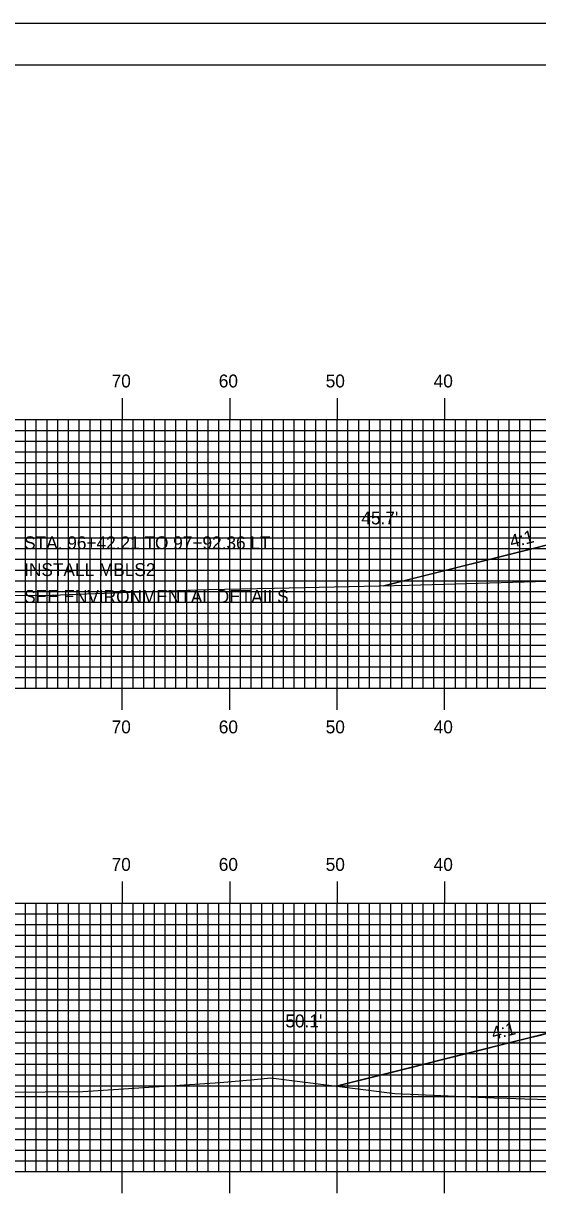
# Model space of a CAD drawing. Extents: x 1765726 to 1766069, y 442591 to 442811.
# Drawn here: x 1765812.7 to 1765860.5, y 442701.2 to 442810.5 of the extents above; entities that cross this region are included whole.
import ezdxf

# ---------------------------------------------------------------- set-up
doc = ezdxf.new("R2010")
doc.units = 0
for name, color, linetype in [('ANNOTATION', 7, 'Continuous'), ('BORDER', 7, 'Continuous'), ('D_Roadway_Centerline', 7, 'Continuous'), ('D_Roadway_SlopeLines', 7, 'Continuous'), ('D_Text_Standard', 7, 'Continuous'), ('H_V ANNOTATION', 7, 'Continuous'), ('MAJOR', 7, 'Continuous'), ('MINOR', 7, 'Continuous'), ('PLOT BOUNDARY', 7, 'Continuous'), ('S_Roadway_Centerline', 7, 'Continuous')]:
    doc.layers.add(name, color=color, linetype=linetype)

msp = doc.modelspace()

# ---------------------------------------------------------------- linework, layer by layer
at = {"layer": 'BORDER'}
msp.add_lwpolyline([(1765742.28, 442596.67), (1766062.28, 442596.67), (1766062.28, 442806.67), (1765742.28, 442806.67)], close=True, dxfattribs=at)
at = {"layer": 'D_Roadway_Centerline'}
for points in [[(1765846.22, 442758.2), (1765848.67, 442758.82), (1765859.88, 442761.62), (1765859.88, 442761.62), (1765861.71, 442762.08), (1765861.71, 442762.08), (1765864.22, 442762.7), (1765871.88, 442764.62), (1765871.88, 442764.62), (1765871.89, 442764.62), (1765879.88, 442764.94), (1765890.42, 442764.71), (1765891.88, 442764.67), (1765891.89, 442764.67), (1765903.88, 442764.41), (1765903.89, 442764.41), (1765907.46, 442764.27), (1765911.88, 442764.09), (1765922.06, 442761.55), (1765930.71, 442759.38), (1765930.71, 442759.38)], [(1765841.8, 442711.63), (1765845.9, 442712.65), (1765859.88, 442716.15), (1765860.72, 442716.36), (1765861.71, 442716.61), (1765865.41, 442717.53), (1765871.88, 442719.15), (1765871.88, 442719.15), (1765878.83, 442719.43), (1765879.88, 442719.47), (1765883.45, 442719.39), (1765891.88, 442719.21), (1765903.88, 442718.94), (1765903.89, 442718.94), (1765909.96, 442718.7), (1765911.88, 442718.62), (1765922.06, 442716.08), (1765935.37, 442712.75)]]:
    msp.add_lwpolyline(points, dxfattribs=at)
at = {"layer": 'D_Roadway_SlopeLines'}
for points in [[(1765871.88, 442764.62), (1765861.71, 442762.08), (1765859.88, 442761.62), (1765846.22, 442758.2)], [(1765871.88, 442719.15), (1765861.71, 442716.61), (1765859.88, 442716.15), (1765841.8, 442711.63)]]:
    msp.add_lwpolyline(points, dxfattribs=at)
at = {"layer": 'MAJOR'}
for p, q in [((1765821.88, 442775.67), (1765821.88, 442773.67)), ((1765831.88, 442775.67), (1765831.88, 442773.67)), ((1765841.88, 442775.67), (1765841.88, 442773.67)), ((1765851.88, 442775.67), (1765851.88, 442773.67)), ((1765751.88, 442773.67), (1766031.88, 442773.67)), ((1765751.88, 442773.67), (1766031.88, 442773.67)), ((1765821.88, 442748.67), (1765821.88, 442773.67)), ((1765831.88, 442748.67), (1765831.88, 442773.67)), ((1765841.88, 442748.67), (1765841.88, 442773.67)), ((1765851.88, 442748.67), (1765851.88, 442773.67)), ((1765751.88, 442768.67), (1766031.88, 442768.67)), ((1765751.88, 442763.67), (1766031.88, 442763.67)), ((1765751.88, 442758.67), (1766031.88, 442758.67)), ((1765751.88, 442753.67), (1766031.88, 442753.67)), ((1765751.88, 442748.67), (1766031.88, 442748.67)), ((1765751.88, 442748.67), (1766031.88, 442748.67)), ((1765821.88, 442746.66), (1765821.88, 442748.67)), ((1765831.88, 442746.66), (1765831.88, 442748.67)), ((1765841.88, 442746.66), (1765841.88, 442748.67)), ((1765851.88, 442746.66), (1765851.88, 442748.67)), ((1765821.88, 442730.67), (1765821.88, 442728.67)), ((1765831.88, 442730.67), (1765831.88, 442728.67)), ((1765841.88, 442730.67), (1765841.88, 442728.67)), ((1765851.88, 442730.67), (1765851.88, 442728.67)), ((1765751.88, 442728.67), (1766031.88, 442728.67)), ((1765751.88, 442728.67), (1766031.88, 442728.67)), ((1765821.88, 442703.67), (1765821.88, 442728.67)), ((1765831.88, 442703.67), (1765831.88, 442728.67)), ((1765841.88, 442703.67), (1765841.88, 442728.67)), ((1765851.88, 442703.67), (1765851.88, 442728.67)), ((1765751.88, 442723.67), (1766031.88, 442723.67)), ((1765751.88, 442718.67), (1766031.88, 442718.67)), ((1765751.88, 442713.67), (1766031.88, 442713.67)), ((1765751.88, 442708.67), (1766031.88, 442708.67)), ((1765751.88, 442703.67), (1766031.88, 442703.67)), ((1765751.88, 442703.67), (1766031.88, 442703.67)), ((1765821.88, 442701.66), (1765821.88, 442703.67)), ((1765831.88, 442701.66), (1765831.88, 442703.67)), ((1765841.88, 442701.66), (1765841.88, 442703.67)), ((1765851.88, 442701.66), (1765851.88, 442703.67))]:
    msp.add_line(p, q, dxfattribs=at)
at = {"layer": 'MINOR'}
for p, q in [((1765812.88, 442748.67), (1765812.88, 442773.67)), ((1765813.88, 442748.67), (1765813.88, 442773.67)), ((1765814.88, 442748.67), (1765814.88, 442773.67)), ((1765815.88, 442748.67), (1765815.88, 442773.67)), ((1765816.88, 442748.67), (1765816.88, 442773.67)), ((1765817.88, 442748.67), (1765817.88, 442773.67)), ((1765818.88, 442748.67), (1765818.88, 442773.67)), ((1765819.88, 442748.67), (1765819.88, 442773.67)), ((1765820.88, 442748.67), (1765820.88, 442773.67)), ((1765822.88, 442748.67), (1765822.88, 442773.67)), ((1765823.88, 442748.67), (1765823.88, 442773.67)), ((1765824.88, 442748.67), (1765824.88, 442773.67)), ((1765825.88, 442748.67), (1765825.88, 442773.67)), ((1765826.88, 442748.67), (1765826.88, 442773.67)), ((1765827.88, 442748.67), (1765827.88, 442773.67)), ((1765828.88, 442748.67), (1765828.88, 442773.67)), ((1765829.88, 442748.67), (1765829.88, 442773.67)), ((1765830.88, 442748.67), (1765830.88, 442773.67)), ((1765832.88, 442748.67), (1765832.88, 442773.67)), ((1765833.88, 442748.67), (1765833.88, 442773.67)), ((1765834.88, 442748.67), (1765834.88, 442773.67)), ((1765835.88, 442748.67), (1765835.88, 442773.67)), ((1765836.88, 442748.67), (1765836.88, 442773.67)), ((1765837.88, 442748.67), (1765837.88, 442773.67)), ((1765838.88, 442748.67), (1765838.88, 442773.67)), ((1765839.88, 442748.67), (1765839.88, 442773.67)), ((1765840.88, 442748.67), (1765840.88, 442773.67)), ((1765842.88, 442748.67), (1765842.88, 442773.67)), ((1765843.88, 442748.67), (1765843.88, 442773.67)), ((1765844.88, 442748.67), (1765844.88, 442773.67)), ((1765845.88, 442748.67), (1765845.88, 442773.67)), ((1765846.88, 442748.67), (1765846.88, 442773.67)), ((1765847.88, 442748.67), (1765847.88, 442773.67)), ((1765848.88, 442748.67), (1765848.88, 442773.67)), ((1765849.88, 442748.67), (1765849.88, 442773.67)), ((1765850.88, 442748.67), (1765850.88, 442773.67)), ((1765852.88, 442748.67), (1765852.88, 442773.67)), ((1765853.88, 442748.67), (1765853.88, 442773.67)), ((1765854.88, 442748.67), (1765854.88, 442773.67)), ((1765855.88, 442748.67), (1765855.88, 442773.67)), ((1765856.88, 442748.67), (1765856.88, 442773.67)), ((1765857.88, 442748.67), (1765857.88, 442773.67)), ((1765858.88, 442748.67), (1765858.88, 442773.67)), ((1765859.88, 442748.67), (1765859.88, 442773.67)), ((1765751.88, 442772.67), (1766031.88, 442772.67)), ((1765751.88, 442771.67), (1766031.88, 442771.67)), ((1765751.88, 442770.67), (1766031.88, 442770.67)), ((1765751.88, 442769.67), (1766031.88, 442769.67)), ((1765751.88, 442767.67), (1766031.88, 442767.67)), ((1765751.88, 442766.67), (1766031.88, 442766.67)), ((1765751.88, 442765.67), (1766031.88, 442765.67)), ((1765751.88, 442764.67), (1766031.88, 442764.67)), ((1765751.88, 442762.67), (1766031.88, 442762.67)), ((1765751.88, 442761.67), (1766031.88, 442761.67)), ((1765751.88, 442760.67), (1766031.88, 442760.67)), ((1765751.88, 442759.67), (1766031.88, 442759.67)), ((1765751.88, 442757.67), (1766031.88, 442757.67)), ((1765751.88, 442756.67), (1766031.88, 442756.67)), ((1765751.88, 442755.67), (1766031.88, 442755.67)), ((1765751.88, 442754.67), (1766031.88, 442754.67)), ((1765751.88, 442752.67), (1766031.88, 442752.67)), ((1765751.88, 442751.67), (1766031.88, 442751.67)), ((1765751.88, 442750.67), (1766031.88, 442750.67)), ((1765751.88, 442749.67), (1766031.88, 442749.67)), ((1765812.88, 442703.67), (1765812.88, 442728.67)), ((1765813.88, 442703.67), (1765813.88, 442728.67)), ((1765814.88, 442703.67), (1765814.88, 442728.67)), ((1765815.88, 442703.67), (1765815.88, 442728.67)), ((1765816.88, 442703.67), (1765816.88, 442728.67)), ((1765817.88, 442703.67), (1765817.88, 442728.67)), ((1765818.88, 442703.67), (1765818.88, 442728.67)), ((1765819.88, 442703.67), (1765819.88, 442728.67)), ((1765820.88, 442703.67), (1765820.88, 442728.67)), ((1765822.88, 442703.67), (1765822.88, 442728.67)), ((1765823.88, 442703.67), (1765823.88, 442728.67)), ((1765824.88, 442703.67), (1765824.88, 442728.67)), ((1765825.88, 442703.67), (1765825.88, 442728.67)), ((1765826.88, 442703.67), (1765826.88, 442728.67)), ((1765827.88, 442703.67), (1765827.88, 442728.67)), ((1765828.88, 442703.67), (1765828.88, 442728.67)), ((1765829.88, 442703.67), (1765829.88, 442728.67)), ((1765830.88, 442703.67), (1765830.88, 442728.67)), ((1765832.88, 442703.67), (1765832.88, 442728.67)), ((1765833.88, 442703.67), (1765833.88, 442728.67)), ((1765834.88, 442703.67), (1765834.88, 442728.67)), ((1765835.88, 442703.67), (1765835.88, 442728.67)), ((1765836.88, 442703.67), (1765836.88, 442728.67)), ((1765837.88, 442703.67), (1765837.88, 442728.67)), ((1765838.88, 442703.67), (1765838.88, 442728.67)), ((1765839.88, 442703.67), (1765839.88, 442728.67)), ((1765840.88, 442703.67), (1765840.88, 442728.67)), ((1765842.88, 442703.67), (1765842.88, 442728.67)), ((1765843.88, 442703.67), (1765843.88, 442728.67)), ((1765844.88, 442703.67), (1765844.88, 442728.67)), ((1765845.88, 442703.67), (1765845.88, 442728.67)), ((1765846.88, 442703.67), (1765846.88, 442728.67)), ((1765847.88, 442703.67), (1765847.88, 442728.67)), ((1765848.88, 442703.67), (1765848.88, 442728.67)), ((1765849.88, 442703.67), (1765849.88, 442728.67)), ((1765850.88, 442703.67), (1765850.88, 442728.67)), ((1765852.88, 442703.67), (1765852.88, 442728.67)), ((1765853.88, 442703.67), (1765853.88, 442728.67)), ((1765854.88, 442703.67), (1765854.88, 442728.67)), ((1765855.88, 442703.67), (1765855.88, 442728.67)), ((1765856.88, 442703.67), (1765856.88, 442728.67)), ((1765857.88, 442703.67), (1765857.88, 442728.67)), ((1765858.88, 442703.67), (1765858.88, 442728.67)), ((1765859.88, 442703.67), (1765859.88, 442728.67)), ((1765751.88, 442727.67), (1766031.88, 442727.67)), ((1765751.88, 442726.67), (1766031.88, 442726.67)), ((1765751.88, 442725.67), (1766031.88, 442725.67)), ((1765751.88, 442724.67), (1766031.88, 442724.67)), ((1765751.88, 442722.67), (1766031.88, 442722.67)), ((1765751.88, 442721.67), (1766031.88, 442721.67)), ((1765751.88, 442720.67), (1766031.88, 442720.67)), ((1765751.88, 442719.67), (1766031.88, 442719.67)), ((1765751.88, 442717.67), (1766031.88, 442717.67)), ((1765751.88, 442716.67), (1766031.88, 442716.67)), ((1765751.88, 442715.67), (1766031.88, 442715.67)), ((1765751.88, 442714.67), (1766031.88, 442714.67)), ((1765751.88, 442712.67), (1766031.88, 442712.67)), ((1765751.88, 442711.67), (1766031.88, 442711.67)), ((1765751.88, 442710.67), (1766031.88, 442710.67)), ((1765751.88, 442709.67), (1766031.88, 442709.67)), ((1765751.88, 442707.67), (1766031.88, 442707.67)), ((1765751.88, 442706.67), (1766031.88, 442706.67)), ((1765751.88, 442705.67), (1766031.88, 442705.67)), ((1765751.88, 442704.67), (1766031.88, 442704.67))]:
    msp.add_line(p, q, dxfattribs=at)
at = {"layer": 'PLOT BOUNDARY'}
msp.add_lwpolyline([(1765726.1, 442590.55), (1766066.1, 442590.55), (1766066.1, 442810.55), (1765726.1, 442810.55)], close=True, dxfattribs=at)
at = {"layer": 'S_Roadway_Centerline'}
for points in [[(1765811.71, 442757.29), (1765815.32, 442757.33), (1765823.43, 442757.64), (1765829.83, 442757.85), (1765836.03, 442758), (1765848.57, 442758.25), (1765860.32, 442758.61), (1765866.57, 442758.79)], [(1765811.19, 442711.08), (1765818.21, 442711.14), (1765830.98, 442711.97), (1765834.15, 442712.24), (1765835.72, 442712.4), (1765847.23, 442710.94), (1765848.7, 442710.88), (1765855.02, 442710.61), (1765855.66, 442710.58), (1765856.53, 442710.55), (1765857.71, 442710.51), (1765859.34, 442710.46), (1765861.7, 442710.38)]]:
    msp.add_lwpolyline(points, dxfattribs=at)

# ---------------------------------------------------------------- texts
at = {"layer": 'ANNOTATION'}
for rotation, p in [(14.035, (1765858.11, 442761.73)), (14.0394, (1765856.41, 442715.94))]:
    msp.add_text('4:1', height=1.2, rotation=rotation, dxfattribs=at).set_placement(p)
at = {"layer": 'D_Text_Standard'}
for s, p in [("45.7'", (1765844.13, 442763.92)), ('STA. 96+42.21 TO 97+92.36 LT.', (1765812.75, 442761.61)), ('INSTALL MBLS2', (1765812.75, 442759.11)), ('SEE ENVIRONMENTAL DETAILS', (1765812.75, 442756.61)), ("50.1'", (1765837.06, 442717.1))]:
    msp.add_text(s, height=1.2, dxfattribs=at).set_placement(p)
at = {"layer": 'H_V ANNOTATION'}
for s, p in [('70', (1765820.89, 442776.67)), ('60', (1765830.86, 442776.67)), ('50', (1765840.81, 442776.67)), ('40', (1765850.86, 442776.67)), ('70', (1765820.89, 442744.47)), ('60', (1765830.86, 442744.47)), ('50', (1765840.81, 442744.47)), ('40', (1765850.86, 442744.47)), ('70', (1765820.89, 442731.67)), ('60', (1765830.86, 442731.67)), ('50', (1765840.81, 442731.67)), ('40', (1765850.86, 442731.67))]:
    msp.add_text(s, height=1.2, dxfattribs=at).set_placement(p)

doc.saveas('drawing.dxf')
